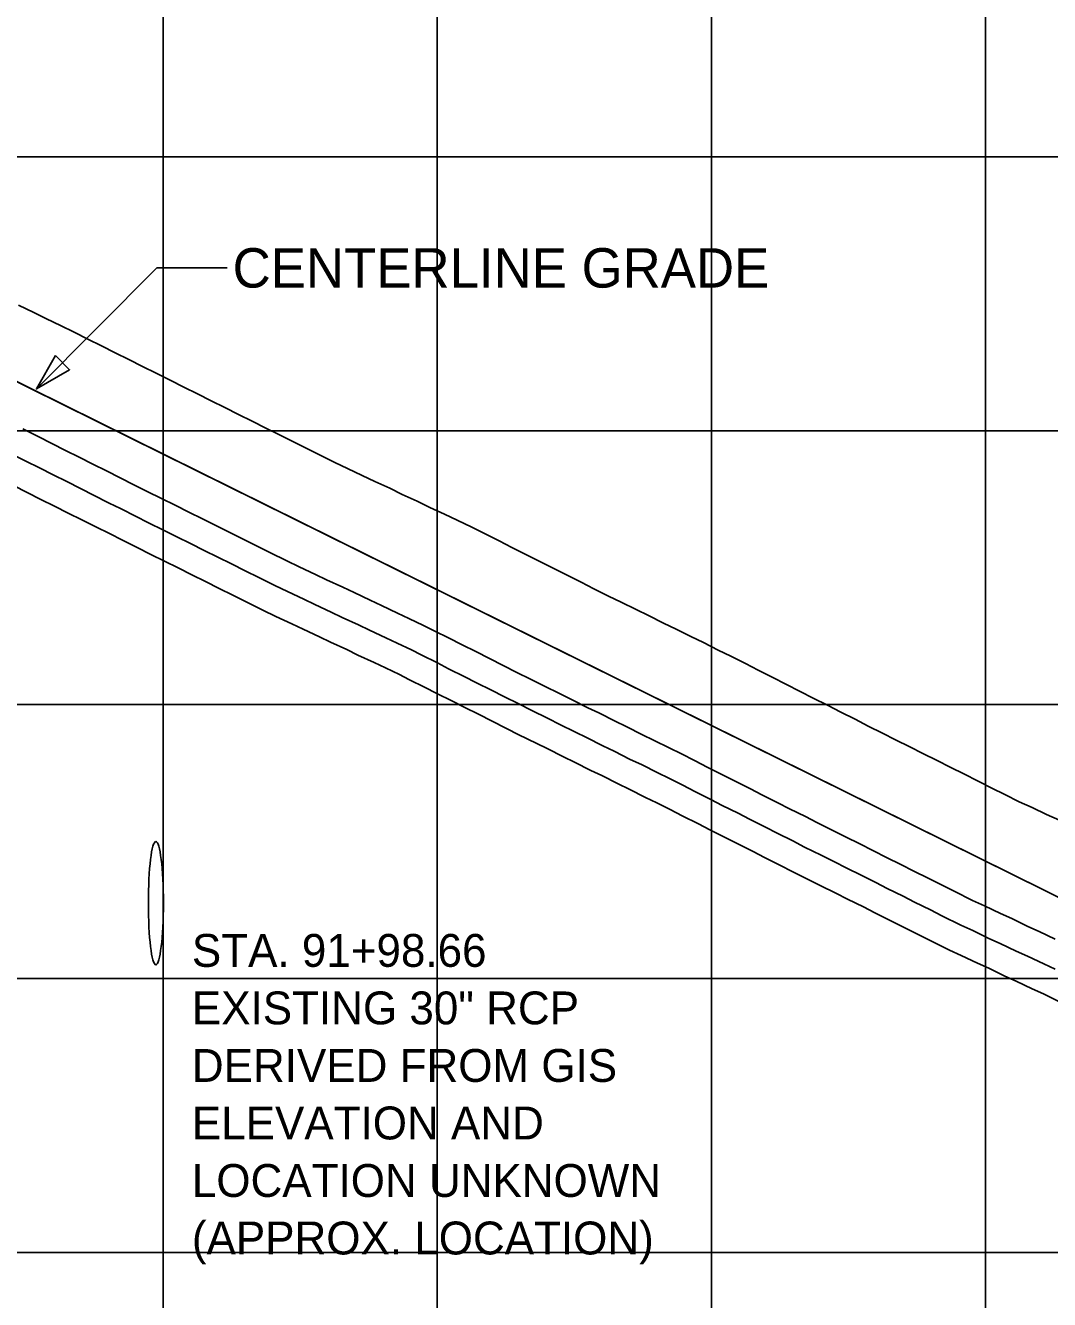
# Model space of a CAD drawing. Extents: x -7164 to 2214450, y -19642 to 253469.
# Drawn here: x 3174.9 to 3361.7, y -2108.6 to -1876 of the extents above; entities that cross this region are included whole.
import ezdxf

# ---------------------------------------------------------------- set-up
doc = ezdxf.new("R2010")
doc.units = 0
for name, color, linetype in [('DESIGN - PROFILE - Proposed', 7, 'Continuous'), ('DESIGN - PROFILE - Proposed Text', 7, 'Continuous'), ('DESIGN - SHEET - Light Grid', 7, 'Continuous'), ('SURVEY - PROFILE - Drainage - Pipes and Culverts', 7, 'Continuous'), ('SURVEY - PROFILE - Drainage - Pipes and Culverts Text', 7, 'Continuous'), ('SURVEY - PROFILE - Ground Line with Text', 7, 'Continuous'), ('SURVEY - PROFILE - Utilities - Cable with Text', 7, 'Continuous'), ('SURVEY - PROFILE - Utilities - Electric with Text', 7, 'Continuous'), ('XTREE', 7, 'Continuous')]:
    doc.layers.add(name, color=color, linetype=linetype)

msp = doc.modelspace()

# ---------------------------------------------------------------- linework, layer by layer
at = {"layer": 'DESIGN - PROFILE - Proposed'}
msp.add_line((2660.96, -1687.48), (3497.5, -2101.57), dxfattribs=at)
msp.add_line((2660.96, -1687.48), (3497.5, -2101.57), dxfattribs=at)
at = {"layer": 'DESIGN - PROFILE - Proposed Text'}
msp.add_lwpolyline([(3211.66, -1920.27), (3198.86, -1920.27), (3176.86, -1942.36)], dxfattribs=at)
msp.add_lwpolyline([(3211.66, -1920.27), (3198.86, -1920.27), (3176.86, -1942.36)], dxfattribs=at)
msp.add_lwpolyline([(3180.35, -1936.29), (3176.86, -1942.36), (3182.92, -1938.85)], close=True, dxfattribs=at)
msp.add_lwpolyline([(3180.35, -1936.29), (3176.86, -1942.36), (3182.92, -1938.85)], close=True, dxfattribs=at)
at = {"layer": 'DESIGN - SHEET - Light Grid'}
for p, q in [((3200, -3000), (3200, -1000)), ((3200, -3000), (3200, -1000)), ((3250, -3000), (3250, -1000)), ((3250, -3000), (3250, -1000)), ((3300, -3000), (3300, -1000)), ((3300, -3000), (3300, -1000)), ((3350, -3000), (3350, -1000)), ((3350, -3000), (3350, -1000)), ((0, -1900), (12400, -1900)), ((0, -1900), (12400, -1900)), ((0, -1950), (12400, -1950)), ((0, -1950), (12400, -1950)), ((0, -2000), (12400, -2000)), ((0, -2000), (12400, -2000)), ((0, -2050), (12400, -2050)), ((0, -2050), (12400, -2050)), ((0, -2100), (12400, -2100)), ((0, -2100), (12400, -2100))]:
    msp.add_line(p, q, dxfattribs=at)
at = {"layer": 'SURVEY - PROFILE - Drainage - Pipes and Culverts'}
msp.add_line((3198.66, -2047.47), (3198.66, -2047.47), dxfattribs=at)
msp.add_line((3198.66, -2047.47), (3198.66, -2047.47), dxfattribs=at)
msp.add_ellipse((3198.66, -2036.22), major_axis=(0, 11.25), ratio=0.122012, dxfattribs=at)
msp.add_ellipse((3198.66, -2036.22), major_axis=(0, 11.25), ratio=0.122012, dxfattribs=at)
at = {"layer": 'SURVEY - PROFILE - Ground Line with Text'}
for points in [[(3173.61, -1927.05), (3176.39, -1928.39), (3178.61, -1929.48), (3181.38, -1930.82), (3183.61, -1931.92), (3186.37, -1933.33), (3188.61, -1934.43), (3191.37, -1935.83), (3193.61, -1936.94)], [(3173.61, -1927.05), (3176.39, -1928.39), (3178.61, -1929.48), (3181.38, -1930.82), (3183.61, -1931.92), (3186.37, -1933.33), (3188.61, -1934.43), (3191.37, -1935.83), (3193.61, -1936.94)], [(3193.61, -1936.94), (3196.36, -1938.34), (3198.62, -1939.45), (3201.36, -1940.85), (3203.62, -1941.96), (3206.35, -1943.35), (3208.62, -1944.49), (3211.34, -1945.84), (3213.62, -1946.98), (3216.34, -1948.33), (3218.62, -1949.47), (3221.33, -1950.81), (3223.62, -1951.96), (3226.33, -1953.3), (3228.62, -1954.46), (3231.32, -1955.79), (3233.62, -1956.9), (3236.31, -1958.15), (3238.62, -1959.26), (3241.31, -1960.51), (3243.61, -1961.62), (3246.3, -1962.87), (3248.61, -1963.98), (3251.3, -1965.23), (3253.61, -1966.34), (3256.29, -1967.59), (3258.6, -1968.77), (3261.29, -1970.11), (3263.59, -1971.29), (3266.28, -1972.63), (3268.58, -1973.81), (3271.27, -1975.15), (3273.58, -1976.33), (3276.27, -1977.66), (3278.57, -1978.85), (3281.26, -1980.18), (3283.56, -1981.28), (3286.25, -1982.65), (3288.55, -1983.75), (3291.25, -1985.11), (3293.55, -1986.21), (3296.24, -1987.58), (3298.54, -1988.68), (3301.24, -1990.04), (3303.54, -1991.14), (3306.23, -1992.51), (3308.55, -1993.73), (3311.22, -1995.04), (3313.56, -1996.27), (3316.22, -1997.57), (3318.58, -1998.82), (3321.21, -2000.11), (3323.59, -2001.36), (3326.2, -2002.65), (3328.61, -2003.91), (3331.2, -2005.18), (3333.61, -2006.41), (3336.19, -2007.69), (3338.59, -2008.91), (3341.19, -2010.2), (3343.58, -2011.42), (3346.18, -2012.71), (3348.56, -2013.92), (3351.17, -2015.22), (3353.55, -2016.42), (3356.17, -2017.73), (3358.54, -2018.78), (3361.16, -2020.06), (3363.53, -2021.11)], [(3193.61, -1936.94), (3196.36, -1938.34), (3198.62, -1939.45), (3201.36, -1940.85), (3203.62, -1941.96), (3206.35, -1943.35), (3208.62, -1944.49), (3211.34, -1945.84), (3213.62, -1946.98), (3216.34, -1948.33), (3218.62, -1949.47), (3221.33, -1950.81), (3223.62, -1951.96), (3226.33, -1953.3), (3228.62, -1954.46), (3231.32, -1955.79), (3233.62, -1956.9), (3236.31, -1958.15), (3238.62, -1959.26), (3241.31, -1960.51), (3243.61, -1961.62), (3246.3, -1962.87), (3248.61, -1963.98), (3251.3, -1965.23), (3253.61, -1966.34), (3256.29, -1967.59), (3258.6, -1968.77), (3261.29, -1970.11), (3263.59, -1971.29), (3266.28, -1972.63), (3268.58, -1973.81), (3271.27, -1975.15), (3273.58, -1976.33), (3276.27, -1977.66), (3278.57, -1978.85), (3281.26, -1980.18), (3283.56, -1981.28), (3286.25, -1982.65), (3288.55, -1983.75), (3291.25, -1985.11), (3293.55, -1986.21), (3296.24, -1987.58), (3298.54, -1988.68), (3301.24, -1990.04), (3303.54, -1991.14), (3306.23, -1992.51), (3308.55, -1993.73), (3311.22, -1995.04), (3313.56, -1996.27), (3316.22, -1997.57), (3318.58, -1998.82), (3321.21, -2000.11), (3323.59, -2001.36), (3326.2, -2002.65), (3328.61, -2003.91), (3331.2, -2005.18), (3333.61, -2006.41), (3336.19, -2007.69), (3338.59, -2008.91), (3341.19, -2010.2), (3343.58, -2011.42), (3346.18, -2012.71), (3348.56, -2013.92), (3351.17, -2015.22), (3353.55, -2016.42), (3356.17, -2017.73), (3358.54, -2018.78), (3361.16, -2020.06), (3363.53, -2021.11)]]:
    msp.add_lwpolyline(points, dxfattribs=at)
at = {"layer": 'SURVEY - PROFILE - Utilities - Cable with Text'}
msp.add_lwpolyline([(3172.94, -1960.14), (3174.94, -1961.12), (3177.94, -1962.65), (3179.94, -1963.63), (3182.93, -1965.16), (3184.94, -1966.15), (3187.93, -1967.67), (3189.94, -1968.66), (3192.8, -1970.12), (3194.99, -1971.21), (3197.96, -1972.68), (3199.98, -1973.7), (3202.96, -1975.17), (3204.98, -1976.19), (3207.95, -1977.65), (3209.98, -1978.68), (3212.94, -1980.14), (3214.98, -1981.17), (3218.18, -1982.75), (3220.54, -1983.88), (3223.49, -1985.25), (3225.54, -1986.24), (3228.49, -1987.61), (3230.53, -1988.59), (3233.48, -1989.96), (3235.53, -1990.95), (3238.48, -1992.32), (3240.52, -1993.3), (3243.12, -1994.51), (3244.81, -1995.38), (3247.76, -1996.85), (3249.8, -1997.89), (3252.76, -1999.36), (3254.79, -2000.41), (3257.75, -2001.88), (3259.79, -2002.92), (3262.74, -2004.39), (3264.78, -2005.43), (3268.13, -2007.1), (3270.04, -2008.01), (3273.01, -2009.52), (3275.04, -2010.49), (3278, -2011.99), (3280.03, -2012.96), (3283, -2014.46), (3285.02, -2015.43), (3287.99, -2016.94), (3290.02, -2017.9), (3292.47, -2019.15), (3294.68, -2020.31), (3297.63, -2021.76), (3299.69, -2022.84), (3302.62, -2024.28), (3304.7, -2025.37), (3307.61, -2026.81), (3309.71, -2027.91), (3312.61, -2029.33), (3314.72, -2030.44), (3317.8, -2031.96), (3319.85, -2033), (3322.73, -2034.43), (3324.83, -2035.5), (3327.72, -2036.93), (3329.82, -2038), (3332.71, -2039.44), (3334.8, -2040.5), (3337.71, -2041.95), (3339.78, -2043), (3343.41, -2044.8), (3345.59, -2045.77), (3348.52, -2047.2), (3350.59, -2048.11), (3353.51, -2049.54), (3355.58, -2050.45), (3358.51, -2051.88), (3360.58, -2052.8), (3363.5, -2054.22)], dxfattribs=at)
msp.add_lwpolyline([(3172.94, -1960.14), (3174.94, -1961.12), (3177.94, -1962.65), (3179.94, -1963.63), (3182.93, -1965.16), (3184.94, -1966.15), (3187.93, -1967.67), (3189.94, -1968.66), (3192.8, -1970.12), (3194.99, -1971.21), (3197.96, -1972.68), (3199.98, -1973.7), (3202.96, -1975.17), (3204.98, -1976.19), (3207.95, -1977.65), (3209.98, -1978.68), (3212.94, -1980.14), (3214.98, -1981.17), (3218.18, -1982.75), (3220.54, -1983.88), (3223.49, -1985.25), (3225.54, -1986.24), (3228.49, -1987.61), (3230.53, -1988.59), (3233.48, -1989.96), (3235.53, -1990.95), (3238.48, -1992.32), (3240.52, -1993.3), (3243.12, -1994.51), (3244.81, -1995.38), (3247.76, -1996.85), (3249.8, -1997.89), (3252.76, -1999.36), (3254.79, -2000.41), (3257.75, -2001.88), (3259.79, -2002.92), (3262.74, -2004.39), (3264.78, -2005.43), (3268.13, -2007.1), (3270.04, -2008.01), (3273.01, -2009.52), (3275.04, -2010.49), (3278, -2011.99), (3280.03, -2012.96), (3283, -2014.46), (3285.02, -2015.43), (3287.99, -2016.94), (3290.02, -2017.9), (3292.47, -2019.15), (3294.68, -2020.31), (3297.63, -2021.76), (3299.69, -2022.84), (3302.62, -2024.28), (3304.7, -2025.37), (3307.61, -2026.81), (3309.71, -2027.91), (3312.61, -2029.33), (3314.72, -2030.44), (3317.8, -2031.96), (3319.85, -2033), (3322.73, -2034.43), (3324.83, -2035.5), (3327.72, -2036.93), (3329.82, -2038), (3332.71, -2039.44), (3334.8, -2040.5), (3337.71, -2041.95), (3339.78, -2043), (3343.41, -2044.8), (3345.59, -2045.77), (3348.52, -2047.2), (3350.59, -2048.11), (3353.51, -2049.54), (3355.58, -2050.45), (3358.51, -2051.88), (3360.58, -2052.8), (3363.5, -2054.22)], dxfattribs=at)
at = {"layer": 'SURVEY - PROFILE - Utilities - Electric with Text'}
for points in [[(3174.41, -1949.66), (3177.42, -1951.2), (3179.42, -1952.18), (3182.42, -1953.7), (3184.42, -1954.69), (3187.41, -1956.21), (3189.42, -1957.2), (3192.4, -1958.72), (3194.42, -1959.72), (3197.32, -1961.19), (3199.45, -1962.27), (3202.42, -1963.73), (3204.45, -1964.75), (3207.42, -1966.22), (3209.45, -1967.24), (3212.41, -1968.71), (3214.44, -1969.73), (3217.4, -1971.19), (3219.44, -1972.22), (3222.56, -1973.76), (3224.82, -1974.84), (3227.77, -1976.21), (3229.81, -1977.2), (3232.76, -1978.57), (3234.81, -1979.55), (3237.76, -1980.92), (3239.8, -1981.91), (3242.75, -1983.28), (3244.8, -1984.26), (3247.51, -1985.52), (3249.32, -1986.45), (3252.27, -1987.92), (3254.31, -1988.97), (3257.27, -1990.43), (3259.3, -1991.48), (3262.26, -1992.95), (3264.29, -1993.99), (3267.25, -1995.46), (3269.29, -1996.51), (3272.51, -1998.11), (3274.46, -1999.04), (3277.43, -2000.55), (3279.45, -2001.51), (3282.42, -2003.02), (3284.45, -2003.99), (3287.41, -2005.49), (3289.44, -2006.46), (3292.41, -2007.96), (3294.43, -2008.93), (3297.06, -2010.26), (3299.22, -2011.4), (3302.16, -2012.84), (3304.22, -2013.93), (3307.16, -2015.37), (3309.23, -2016.46), (3312.15, -2017.89), (3314.24, -2018.99), (3317.14, -2020.42), (3319.25, -2021.53), (3322.27, -2023.01), (3324.34, -2024.06), (3327.22, -2025.49), (3329.32, -2026.56), (3332.21, -2028), (3334.31, -2029.06), (3337.2, -2030.51), (3339.29, -2031.56), (3342.2, -2033.01), (3344.27, -2034.06), (3347.66, -2035.75), (3349.81, -2036.7), (3352.73, -2038.13), (3354.8, -2039.04), (3357.73, -2040.47), (3359.8, -2041.38), (3362.72, -2042.81)], [(3174.41, -1949.66), (3177.42, -1951.2), (3179.42, -1952.18), (3182.42, -1953.7), (3184.42, -1954.69), (3187.41, -1956.21), (3189.42, -1957.2), (3192.4, -1958.72), (3194.42, -1959.72), (3197.32, -1961.19), (3199.45, -1962.27), (3202.42, -1963.73), (3204.45, -1964.75), (3207.42, -1966.22), (3209.45, -1967.24), (3212.41, -1968.71), (3214.44, -1969.73), (3217.4, -1971.19), (3219.44, -1972.22), (3222.56, -1973.76), (3224.82, -1974.84), (3227.77, -1976.21), (3229.81, -1977.2), (3232.76, -1978.57), (3234.81, -1979.55), (3237.76, -1980.92), (3239.8, -1981.91), (3242.75, -1983.28), (3244.8, -1984.26), (3247.51, -1985.52), (3249.32, -1986.45), (3252.27, -1987.92), (3254.31, -1988.97), (3257.27, -1990.43), (3259.3, -1991.48), (3262.26, -1992.95), (3264.29, -1993.99), (3267.25, -1995.46), (3269.29, -1996.51), (3272.51, -1998.11), (3274.46, -1999.04), (3277.43, -2000.55), (3279.45, -2001.51), (3282.42, -2003.02), (3284.45, -2003.99), (3287.41, -2005.49), (3289.44, -2006.46), (3292.41, -2007.96), (3294.43, -2008.93), (3297.06, -2010.26), (3299.22, -2011.4), (3302.16, -2012.84), (3304.22, -2013.93), (3307.16, -2015.37), (3309.23, -2016.46), (3312.15, -2017.89), (3314.24, -2018.99), (3317.14, -2020.42), (3319.25, -2021.53), (3322.27, -2023.01), (3324.34, -2024.06), (3327.22, -2025.49), (3329.32, -2026.56), (3332.21, -2028), (3334.31, -2029.06), (3337.2, -2030.51), (3339.29, -2031.56), (3342.2, -2033.01), (3344.27, -2034.06), (3347.66, -2035.75), (3349.81, -2036.7), (3352.73, -2038.13), (3354.8, -2039.04), (3357.73, -2040.47), (3359.8, -2041.38), (3362.72, -2042.81)], [(3172.17, -1954.13), (3175.18, -1955.67), (3177.18, -1956.65), (3180.18, -1958.18), (3182.18, -1959.16), (3185.17, -1960.69), (3187.18, -1961.68), (3190.16, -1963.19), (3192.18, -1964.19), (3195.06, -1965.65), (3197.22, -1966.74), (3200.19, -1968.21), (3202.22, -1969.23), (3205.19, -1970.69), (3207.21, -1971.72), (3210.18, -1973.18), (3212.21, -1974.2), (3215.17, -1975.67), (3217.21, -1976.69), (3220.37, -1978.25), (3222.68, -1979.36), (3225.63, -1980.73), (3227.67, -1981.72), (3230.62, -1983.09), (3232.67, -1984.07), (3235.62, -1985.44), (3237.66, -1986.43), (3240.61, -1987.8), (3242.66, -1988.78), (3245.31, -1990.02), (3247.07, -1990.92), (3250.02, -1992.38), (3252.06, -1993.43), (3255.01, -1994.9), (3257.05, -1995.94), (3260.01, -1997.41), (3262.04, -1998.46), (3265, -1999.93), (3267.03, -2000.97), (3270.32, -2002.6), (3272.25, -2003.53), (3275.22, -2005.03), (3277.24, -2006), (3280.21, -2007.5), (3282.24, -2008.47), (3285.2, -2009.98), (3287.23, -2010.94), (3290.2, -2012.45), (3292.23, -2013.42), (3294.77, -2014.7), (3296.95, -2015.85), (3299.9, -2017.3), (3301.96, -2018.38), (3304.89, -2019.82), (3306.97, -2020.92), (3309.88, -2022.35), (3311.98, -2023.45), (3314.87, -2024.87), (3316.99, -2025.99), (3320.03, -2027.48), (3322.09, -2028.53), (3324.97, -2029.96), (3327.08, -2031.03), (3329.97, -2032.47), (3332.06, -2033.53), (3334.96, -2034.97), (3337.04, -2036.03), (3339.95, -2037.48), (3342.03, -2038.53), (3345.53, -2040.28), (3347.7, -2041.23), (3350.63, -2042.66), (3352.7, -2043.58), (3355.62, -2045), (3357.69, -2045.92), (3360.62, -2047.34), (3362.69, -2048.26)], [(3172.17, -1954.13), (3175.18, -1955.67), (3177.18, -1956.65), (3180.18, -1958.18), (3182.18, -1959.16), (3185.17, -1960.69), (3187.18, -1961.68), (3190.16, -1963.19), (3192.18, -1964.19), (3195.06, -1965.65), (3197.22, -1966.74), (3200.19, -1968.21), (3202.22, -1969.23), (3205.19, -1970.69), (3207.21, -1971.72), (3210.18, -1973.18), (3212.21, -1974.2), (3215.17, -1975.67), (3217.21, -1976.69), (3220.37, -1978.25), (3222.68, -1979.36), (3225.63, -1980.73), (3227.67, -1981.72), (3230.62, -1983.09), (3232.67, -1984.07), (3235.62, -1985.44), (3237.66, -1986.43), (3240.61, -1987.8), (3242.66, -1988.78), (3245.31, -1990.02), (3247.07, -1990.92), (3250.02, -1992.38), (3252.06, -1993.43), (3255.01, -1994.9), (3257.05, -1995.94), (3260.01, -1997.41), (3262.04, -1998.46), (3265, -1999.93), (3267.03, -2000.97), (3270.32, -2002.6), (3272.25, -2003.53), (3275.22, -2005.03), (3277.24, -2006), (3280.21, -2007.5), (3282.24, -2008.47), (3285.2, -2009.98), (3287.23, -2010.94), (3290.2, -2012.45), (3292.23, -2013.42), (3294.77, -2014.7), (3296.95, -2015.85), (3299.9, -2017.3), (3301.96, -2018.38), (3304.89, -2019.82), (3306.97, -2020.92), (3309.88, -2022.35), (3311.98, -2023.45), (3314.87, -2024.87), (3316.99, -2025.99), (3320.03, -2027.48), (3322.09, -2028.53), (3324.97, -2029.96), (3327.08, -2031.03), (3329.97, -2032.47), (3332.06, -2033.53), (3334.96, -2034.97), (3337.04, -2036.03), (3339.95, -2037.48), (3342.03, -2038.53), (3345.53, -2040.28), (3347.7, -2041.23), (3350.63, -2042.66), (3352.7, -2043.58), (3355.62, -2045), (3357.69, -2045.92), (3360.62, -2047.34), (3362.69, -2048.26)]]:
    msp.add_lwpolyline(points, dxfattribs=at)
at = {"layer": 'XTREE'}
msp.add_line((2273.46, -1495.67), (3810, -2256.26), dxfattribs=at)
msp.add_line((2273.46, -1495.67), (3810, -2256.26), dxfattribs=at)

# ---------------------------------------------------------------- texts
at = {"layer": 'DESIGN - PROFILE - Proposed Text'}
msp.add_text('CENTERLINE GRADE', height=7.2, dxfattribs=at).set_placement((3212.66, -1923.87))
msp.add_text('CENTERLINE GRADE', height=7.2, dxfattribs=at).set_placement((3212.66, -1923.87))
at = {"layer": 'SURVEY - PROFILE - Drainage - Pipes and Culverts Text'}
for s, p in [('STA. 91+98.66', (3205.23, -2047.86)), ('STA. 91+98.66', (3205.23, -2047.86)), ('EXISTING 30" RCP', (3205.23, -2058.36)), ('EXISTING 30" RCP', (3205.23, -2058.36)), ('DERIVED FROM GIS', (3205.23, -2068.86)), ('DERIVED FROM GIS', (3205.23, -2068.86)), ('ELEVATION AND ', (3205.23, -2079.36)), ('ELEVATION AND ', (3205.23, -2079.36)), ('LOCATION UNKNOWN', (3205.23, -2089.86)), ('LOCATION UNKNOWN', (3205.23, -2089.86)), ('(APPROX. LOCATION)', (3205.23, -2100.36)), ('(APPROX. LOCATION)', (3205.23, -2100.36))]:
    msp.add_text(s, height=6, dxfattribs=at).set_placement(p)

doc.saveas('drawing.dxf')
